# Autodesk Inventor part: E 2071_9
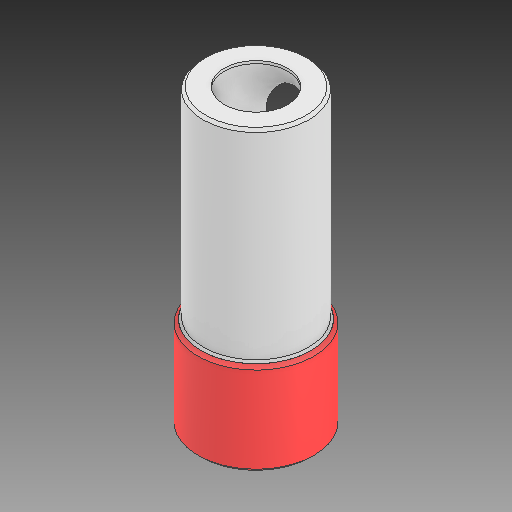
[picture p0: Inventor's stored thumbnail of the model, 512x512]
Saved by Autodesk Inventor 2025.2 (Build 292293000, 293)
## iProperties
Created: 2025-04
Part Number: E 2071_9
Material: Všeobecné
Document SubType Name: Modeling
Designer: Patrik
Density: 1 g/cm^3
Appearance: Výchozí
Mass: 15.5931 g
Surface Area: 50.4471 cm^2
Volume: 15.5931 cm^3
Author: Patrik
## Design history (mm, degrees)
feature "Base1"
node "Těleso1"
